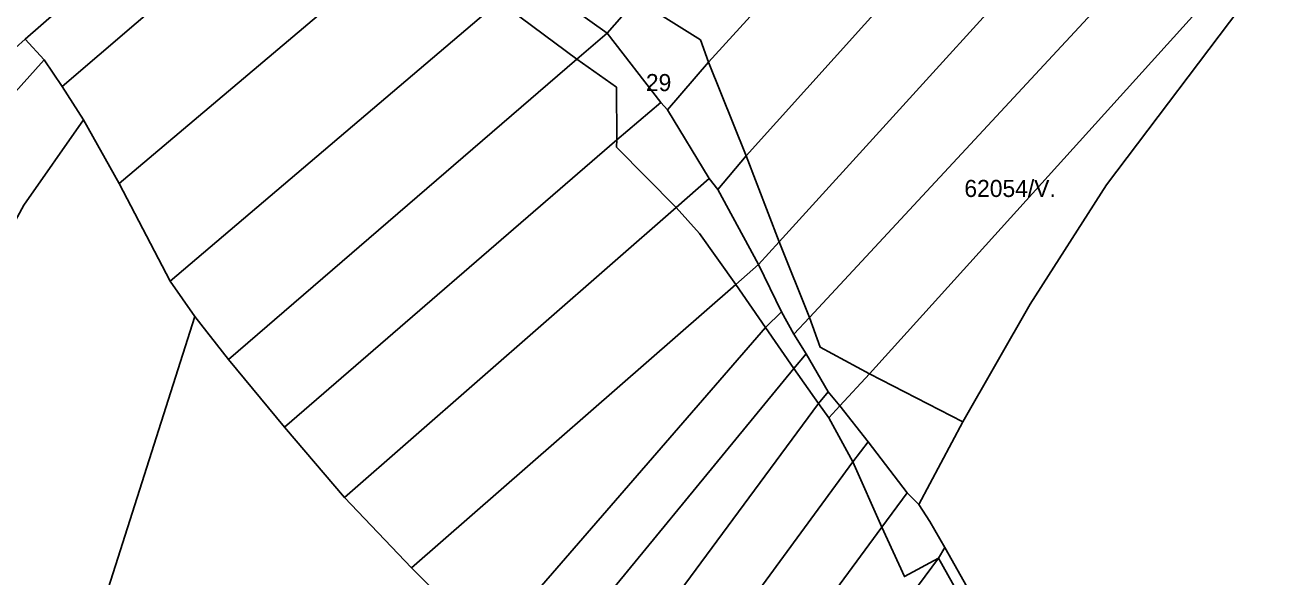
# Model space of a CAD drawing. Extents: x -521261 to -517465, y -1182764 to -1179456.
# Drawn here: x -519282.9 to -518914.6, y -1180527.3 to -1180365.6 of the extents above; entities that cross this region are included whole.
import ezdxf

# ---------------------------------------------------------------- set-up
doc = ezdxf.new("R2010")
doc.units = 0
for name, color, linetype in [('95560013', 7, 'Continuous'), ('95640013', 7, 'Continuous'), ('95660013', 7, 'Continuous')]:
    doc.layers.add(name, color=color, linetype=linetype)

msp = doc.modelspace()

# ---------------------------------------------------------------- linework, layer by layer
at = {"layer": '95560013'}
for points in [[(-519010.01, -1180267.06), (-518995.08, -1180280.28), (-519082.74, -1180376.5), (-519085.15, -1180369.94), (-519103.8, -1180358.17), (-519015.36, -1180262.2)], [(-518995.08, -1180280.28), (-518992.47, -1180282.53), (-518983.19, -1180290.9), (-518975.76, -1180297.28), (-519071.7, -1180403.95), (-519082.74, -1180376.5)], [(-518872.62, -1180293.06), (-518924.13, -1180356.64), (-518966.24, -1180412.4), (-518988.53, -1180447.41), (-519008.28, -1180481.84), (-519035.64, -1180467.78), (-518923.7, -1180343.73), (-518876.88, -1180291.05)], [(-519194.54, -1180297.83), (-519193.89, -1180297.38), (-519184.62, -1180308.69), (-519272, -1180383.57), (-519277.33, -1180375.77), (-519282.81, -1180369.73), (-519249.16, -1180340.26), (-519217.64, -1180314.85), (-519194.84, -1180298.72)], [(-518975.76, -1180297.28), (-518974.28, -1180298.61), (-518957.32, -1180313.77), (-519062.09, -1180429.12), (-519071.7, -1180403.95)], [(-519184.62, -1180308.69), (-519176.29, -1180327.1), (-519168.04, -1180338.25), (-519255.35, -1180412.02), (-519265.72, -1180393.34), (-519272, -1180383.57)], [(-518939.93, -1180329.25), (-519053.22, -1180451.28), (-519062.09, -1180429.12), (-518957.32, -1180313.77)], [(-518923.7, -1180343.73), (-519035.64, -1180467.78), (-519050.07, -1180460), (-519053.22, -1180451.28), (-518939.93, -1180329.25)], [(-519168.04, -1180338.25), (-519163.2, -1180344.4), (-519144.03, -1180358.73), (-519240.36, -1180440.61), (-519255.35, -1180412.02)], [(-519144.03, -1180358.73), (-519121.36, -1180375.58), (-519223.33, -1180463.53), (-519233.13, -1180450.99), (-519240.36, -1180440.61)], [(-519272, -1180383.57), (-519265.72, -1180393.34), (-519283.19, -1180418.4), (-519300.94, -1180450.78), (-519312.32, -1180478.8), (-519321.56, -1180509.65), (-519332.43, -1180567.02), (-519336.13, -1180625.82), (-519381.66, -1180612.73), (-519382.23, -1180569.2), (-519377.41, -1180532.7), (-519370.82, -1180510.84), (-519347.38, -1180464.61), (-519307.06, -1180411.21), (-519293.42, -1180393.67), (-519277.33, -1180375.77)], [(-519121.36, -1180375.58), (-519109.72, -1180383.83), (-519109.62, -1180399.25), (-519206.92, -1180483.41), (-519223.33, -1180463.53)], [(-519265.72, -1180393.34), (-519255.35, -1180412.02), (-519240.36, -1180440.61), (-519233.13, -1180450.99), (-519293.11, -1180638.89), (-519336.13, -1180625.82), (-519332.43, -1180567.02), (-519321.56, -1180509.65), (-519312.32, -1180478.8), (-519300.94, -1180450.78), (-519283.19, -1180418.4)], [(-519109.62, -1180399.25), (-519109.67, -1180401.34), (-519092.23, -1180419.01), (-519189.37, -1180503.99), (-519206.92, -1180483.41)], [(-519092.23, -1180419.01), (-519085.36, -1180426.67), (-519074.75, -1180441.61), (-519169.7, -1180524.6), (-519189.37, -1180503.99)], [(-519074.75, -1180441.61), (-519066.1, -1180454.21), (-519206.13, -1180615.83), (-519210.1, -1180619.68), (-519198.46, -1180598.79), (-519163.85, -1180555.26), (-519155.37, -1180538.92), (-519169.7, -1180524.6)], [(-519233.13, -1180450.99), (-519223.33, -1180463.53), (-519206.92, -1180483.41), (-519189.37, -1180503.99), (-519169.7, -1180524.6), (-519155.37, -1180538.92), (-519163.85, -1180555.26), (-519198.46, -1180598.79), (-519210.1, -1180619.68), (-519214.62, -1180628.5), (-519220.68, -1180646.69), (-519235.13, -1180645.15), (-519284.06, -1180641.39), (-519293.11, -1180638.89)], [(-519066.1, -1180454.21), (-519057.81, -1180466.19), (-519201.63, -1180641.6), (-519204, -1180640.65), (-519220.68, -1180646.69), (-519214.62, -1180628.5), (-519210.1, -1180619.68), (-519206.13, -1180615.83)], [(-519057.81, -1180466.19), (-519050.56, -1180476.44), (-519178.7, -1180650.07), (-519201.63, -1180641.6)], [(-519050.56, -1180476.44), (-519047.53, -1180480.71), (-519040.51, -1180493.58), (-519160.17, -1180656.97), (-519178.7, -1180650.07)], [(-519040.51, -1180493.58), (-519032.04, -1180512.65), (-519143, -1180663.69), (-519160.17, -1180656.97)], [(-519025.42, -1180527.18), (-519015.39, -1180521.74), (-519072.92, -1180599.44), (-519095.94, -1180630.44), (-519119.41, -1180672.22), (-519124.23, -1180670.51), (-519126.4, -1180669.56), (-519143, -1180663.69), (-519032.04, -1180512.65)], [(-518995.4, -1180557.56), (-518983.49, -1180586.91), (-519021.63, -1180630.34), (-519052.05, -1180668.61), (-519097.2, -1180680.42), (-519119.41, -1180672.22), (-519095.94, -1180630.44), (-519072.92, -1180599.44), (-519015.39, -1180521.74)]]:
    msp.add_lwpolyline(points, close=True, dxfattribs=at)
msp.add_lwpolyline([(-518912.15, -1180557.37), (-518933.81, -1180591.04), (-518938.01, -1180602.29), (-518951.28, -1180590.32), (-518960.78, -1180581.34), (-518962.6, -1180579.56), (-518964.48, -1180579.13), (-518975.87, -1180577.02), (-518981.52, -1180575.61), (-519013.54, -1180518.68), (-519017.95, -1180511.02), (-519021.16, -1180506.1), (-519008.28, -1180481.84), (-518988.53, -1180447.41), (-518966.24, -1180412.4), (-518924.13, -1180356.64), (-518872.62, -1180293.06)], dxfattribs=at)
at = {"layer": '95640013'}
msp.add_lwpolyline([(-519249.16, -1180340.26), (-519282.81, -1180369.73), (-519288.55, -1180374.8)], dxfattribs=at)
for points in [[(-519133.4, -1180352.94), (-519125.66, -1180344.01), (-519103.8, -1180358.17), (-519112.46, -1180368.03)], [(-519133.4, -1180352.94), (-519112.46, -1180368.03), (-519121.36, -1180375.58), (-519144.03, -1180358.73), (-519135.45, -1180351.52)], [(-519112.46, -1180368.03), (-519103.8, -1180358.17), (-519085.15, -1180369.94), (-519082.74, -1180376.5), (-519094.78, -1180390.49), (-519096.69, -1180388.33)], [(-519121.36, -1180375.58), (-519112.46, -1180368.03), (-519096.69, -1180388.33), (-519109.62, -1180399.25), (-519109.72, -1180383.83)], [(-519288.55, -1180374.8), (-519282.81, -1180369.73), (-519277.33, -1180375.77), (-519293.42, -1180393.67), (-519307.06, -1180411.21), (-519317.6, -1180400.45)], [(-519094.78, -1180390.49), (-519082.74, -1180376.5), (-519071.7, -1180403.95), (-519080.02, -1180413.74), (-519082.56, -1180410.57)], [(-519094.78, -1180390.49), (-519082.56, -1180410.57), (-519092.23, -1180419.01), (-519109.67, -1180401.34), (-519109.62, -1180399.25), (-519096.69, -1180388.33)], [(-519080.02, -1180413.74), (-519071.7, -1180403.95), (-519062.09, -1180429.12), (-519068.14, -1180435.77)], [(-519080.02, -1180413.74), (-519068.14, -1180435.77), (-519074.75, -1180441.61), (-519085.36, -1180426.67), (-519092.23, -1180419.01), (-519082.56, -1180410.57)], [(-519068.14, -1180435.77), (-519062.09, -1180429.12), (-519053.22, -1180451.28), (-519057.74, -1180456.16), (-519061.43, -1180449.63)], [(-519068.14, -1180435.77), (-519061.43, -1180449.63), (-519066.1, -1180454.21), (-519074.75, -1180441.61)], [(-519061.43, -1180449.63), (-519057.74, -1180456.16), (-519054.19, -1180461.95), (-519057.81, -1180466.19), (-519066.1, -1180454.21)], [(-519057.74, -1180456.16), (-519053.22, -1180451.28), (-519050.07, -1180460), (-519035.64, -1180467.78), (-519044.26, -1180477.18), (-519047.73, -1180473.02), (-519054.19, -1180461.95)], [(-519054.19, -1180461.95), (-519047.73, -1180473.02), (-519050.56, -1180476.44), (-519057.81, -1180466.19)], [(-519035.64, -1180467.78), (-519008.28, -1180481.84), (-519021.16, -1180506.1), (-519024.58, -1180502.59), (-519036.03, -1180487.73), (-519044.26, -1180477.18)], [(-519050.56, -1180476.44), (-519047.73, -1180473.02), (-519044.26, -1180477.18), (-519047.53, -1180480.71)], [(-519047.53, -1180480.71), (-519044.26, -1180477.18), (-519036.03, -1180487.73), (-519040.51, -1180493.58)], [(-519040.51, -1180493.58), (-519036.03, -1180487.73), (-519024.58, -1180502.59), (-519032.04, -1180512.65)], [(-519024.58, -1180502.59), (-519021.16, -1180506.1), (-519017.95, -1180511.02), (-519013.54, -1180518.68), (-519015.39, -1180521.74), (-519025.42, -1180527.18), (-519032.04, -1180512.65)], [(-519015.39, -1180521.74), (-519013.54, -1180518.68), (-518981.52, -1180575.61), (-518975.87, -1180577.02), (-518983.49, -1180586.91), (-518995.4, -1180557.56)]]:
    msp.add_lwpolyline(points, close=True, dxfattribs=at)
at = {"layer": '95660013'}
for points in [[(-519103.8, -1180358.17), (-519085.15, -1180369.94), (-519082.74, -1180376.5), (-519071.7, -1180403.95), (-519062.09, -1180429.12), (-519053.22, -1180451.28), (-519050.07, -1180460), (-519035.64, -1180467.78), (-519008.28, -1180481.84), (-519021.16, -1180506.1), (-519017.95, -1180511.02), (-519013.54, -1180518.68), (-519015.39, -1180521.74), (-519025.42, -1180527.18), (-519032.04, -1180512.65), (-519040.51, -1180493.58), (-519047.53, -1180480.71), (-519050.56, -1180476.44), (-519057.81, -1180466.19), (-519066.1, -1180454.21), (-519074.75, -1180441.61), (-519085.36, -1180426.67), (-519092.23, -1180419.01), (-519109.67, -1180401.34), (-519109.62, -1180399.25), (-519109.72, -1180383.83), (-519121.36, -1180375.58), (-519144.03, -1180358.73)], [(-519144.03, -1180358.73), (-519121.36, -1180375.58), (-519109.72, -1180383.83), (-519109.62, -1180399.25), (-519109.67, -1180401.34), (-519092.23, -1180419.01), (-519085.36, -1180426.67), (-519074.75, -1180441.61), (-519066.1, -1180454.21), (-519057.81, -1180466.19), (-519050.56, -1180476.44), (-519047.53, -1180480.71), (-519040.51, -1180493.58), (-519032.04, -1180512.65), (-519025.42, -1180527.18), (-519015.39, -1180521.74), (-519013.54, -1180518.68), (-519017.95, -1180511.02), (-519021.16, -1180506.1), (-519008.28, -1180481.84), (-519035.64, -1180467.78), (-519050.07, -1180460), (-519053.22, -1180451.28), (-519062.09, -1180429.12), (-519071.7, -1180403.95), (-519082.74, -1180376.5), (-519085.15, -1180369.94), (-519103.8, -1180358.17)]]:
    msp.add_lwpolyline(points, dxfattribs=at)

# ---------------------------------------------------------------- texts
for s, p in [('29', (-519101.09, -1180384.96)), ('62054/V.', (-519007.84, -1180415.97))]:
    msp.add_text(s, height=5, rotation=360, dxfattribs=at).set_placement(p)

doc.saveas('drawing.dxf')
